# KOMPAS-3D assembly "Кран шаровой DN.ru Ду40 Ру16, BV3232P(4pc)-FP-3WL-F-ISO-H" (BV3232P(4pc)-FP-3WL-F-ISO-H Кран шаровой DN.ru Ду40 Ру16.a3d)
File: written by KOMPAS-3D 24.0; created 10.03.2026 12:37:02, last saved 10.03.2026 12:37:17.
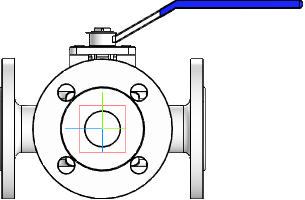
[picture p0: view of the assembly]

Document properties: Автор: R2D2; Полное имя файла: E:\Работа\Зайцев\BV3232P(4pc)-FP-3WL-F-ISO-H Кран шаровой DN.ru Ду15-100 Ру16\DN40\исходные материалы\BV3232P(4pc)-FP-3WL-F-ISO-H Кран шаровой DN.ru Ду40 Ру16.a3d

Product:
- Component [assembly]: Сборка1  | qty 1  | Масса: 13.980546; Автор: R2D2; source file: dn40_3d_step.a3d
- Part/product: Кран шаровой DN.ru Ду40 Ру16  | designation BV3232P(4pc)-FP-3WL-F-ISO-H
    Масса: 11.65
    Раздел спецификации: Прочие изделия
    Примечание: D160-36359

Referenced files in E:\Работа\Зайцев\BV3232P(4pc)-FP-3WL-F-ISO-H Кран шаровой DN.ru Ду15-100 Ру16\DN40\исходные материалы\: dn40_3d_step.a3d
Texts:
  BV3232P(4pc)-FP-3WL-F-ISO-H
  Сборка1 Сборка1
  Ось Z.Начало координат
  Ось Y.Начало координат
